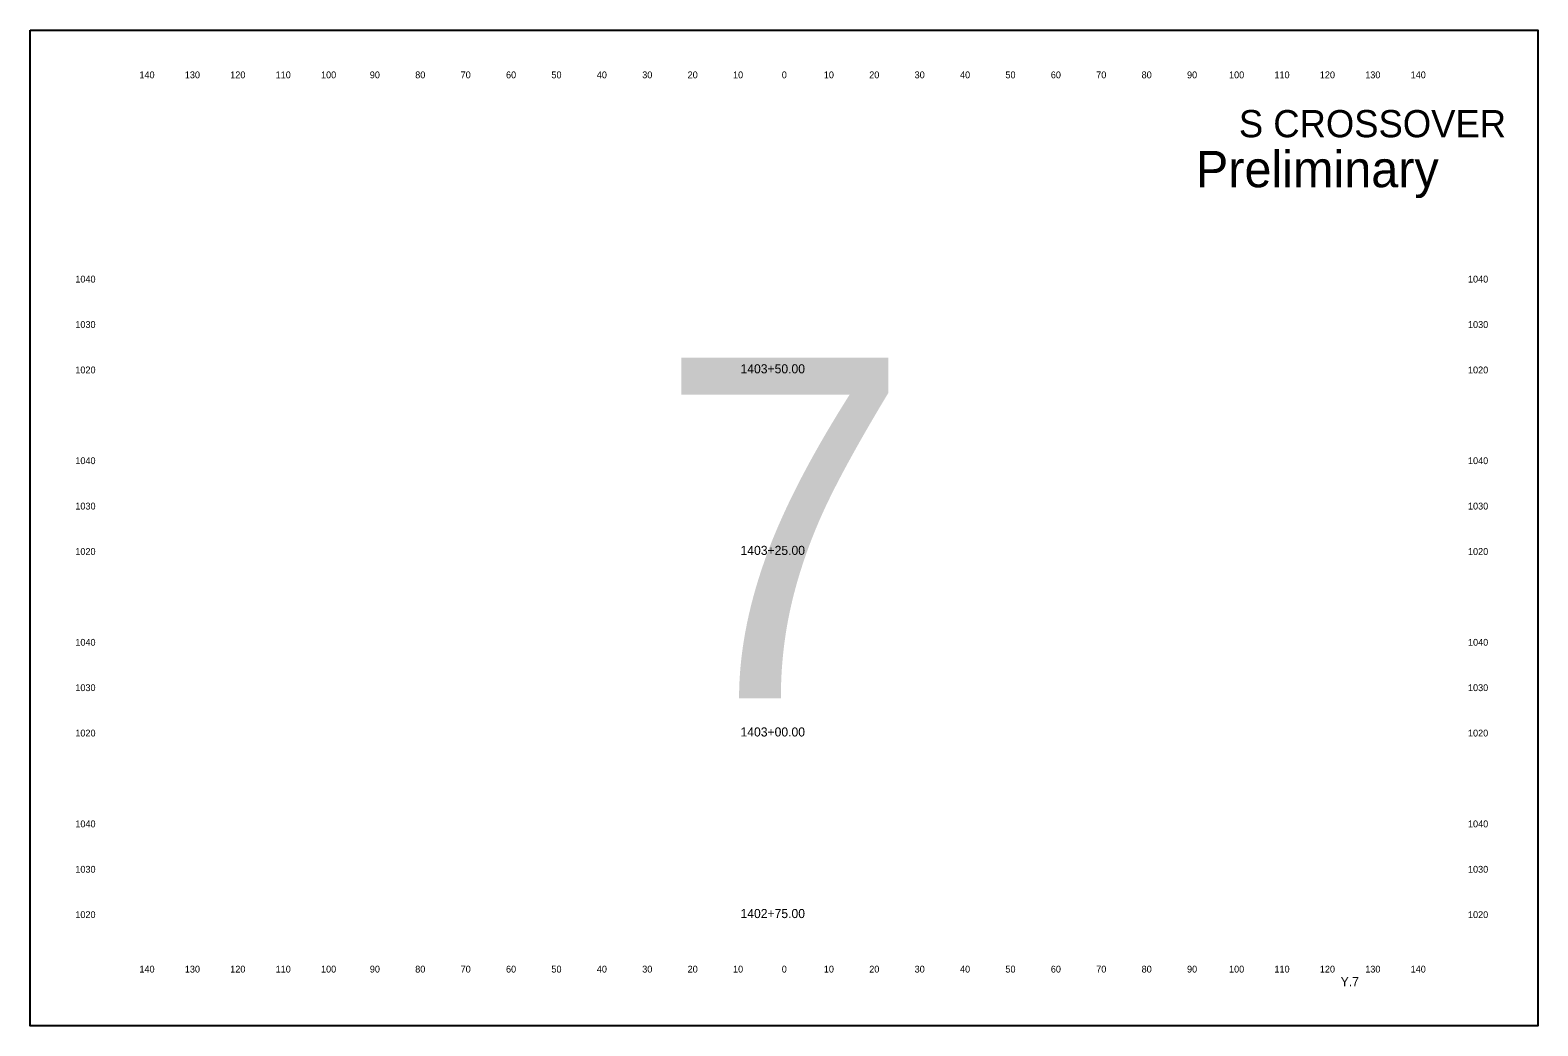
# Model space of a CAD drawing. Extents: x 10123 to 14768, y 9730 to 9950.
# Drawn here: x 12283.2 to 12615.3, y 9730.3 to 9949.6 of the extents above; entities that cross this region are included whole.
import ezdxf

# ---------------------------------------------------------------- set-up
doc = ezdxf.new("R2010")
doc.units = 0
for name, color, linetype in [('dsnTextCpn', 7, 'Continuous'), ('dsnTextCpnTitleSheetLocDesc', 7, 'Continuous'), ('dsnTextCpnTitleSheetPIN', 7, 'Continuous'), ('dsnTextCpnTitleSheetWorkType', 7, 'Continuous')]:
    doc.layers.add(name, color=color, linetype=linetype)

msp = doc.modelspace()

# ---------------------------------------------------------------- linework, layer by layer
at = {"layer": 'dsnTextCpnTitleSheetWorkType'}
msp.add_lwpolyline([(12283.21, 9949.6), (12615.29, 9949.6), (12615.29, 9730.26), (12283.21, 9730.26)], close=True, dxfattribs=at)

# ---------------------------------------------------------------- texts
at = {"layer": 'dsnTextCpn'}
for s, height, p in [('140', 1.5, (12307.27, 9939)), ('130', 1.5, (12317.27, 9939)), ('120', 1.5, (12327.27, 9939)), ('110', 1.5, (12337.27, 9939)), ('100', 1.5, (12347.27, 9939)), ('90', 1.5, (12358.02, 9939)), ('80', 1.5, (12368.02, 9939)), ('70', 1.5, (12378.02, 9939)), ('60', 1.5, (12388.02, 9939)), ('50', 1.5, (12398.02, 9939)), ('40', 1.5, (12408.02, 9939)), ('30', 1.5, (12418.02, 9939)), ('20', 1.5, (12428.02, 9939)), ('10', 1.5, (12438.02, 9939)), ('0', 1.5, (12448.76, 9939)), ('0', 1.5, (12448.76, 9939)), ('10', 1.5, (12458.02, 9939)), ('20', 1.5, (12468.02, 9939)), ('30', 1.5, (12478.02, 9939)), ('40', 1.5, (12488.02, 9939)), ('50', 1.5, (12498.02, 9939)), ('60', 1.5, (12508.02, 9939)), ('70', 1.5, (12518.02, 9939)), ('80', 1.5, (12528.02, 9939)), ('90', 1.5, (12538.02, 9939)), ('100', 1.5, (12547.27, 9939)), ('110', 1.5, (12557.27, 9939)), ('120', 1.5, (12567.27, 9939)), ('130', 1.5, (12577.27, 9939)), ('140', 1.5, (12587.27, 9939)), ('S CROSSOVER', 6, (12549.44, 9926)), ('1040', 1.5, (12293.15, 9894)), ('1040', 1.5, (12599.9, 9894)), ('1030', 1.5, (12293.15, 9884)), ('1030', 1.5, (12599.9, 9884)), ('1020', 1.5, (12293.15, 9874)), ('1403+50.00', 2, (12439.67, 9874)), ('1020', 1.5, (12599.9, 9874)), ('1040', 1.5, (12293.15, 9854)), ('1040', 1.5, (12599.9, 9854)), ('1030', 1.5, (12293.15, 9844)), ('1030', 1.5, (12599.9, 9844)), ('1020', 1.5, (12293.15, 9834)), ('1403+25.00', 2, (12439.67, 9834)), ('1020', 1.5, (12599.9, 9834)), ('1040', 1.5, (12293.15, 9814)), ('1040', 1.5, (12599.9, 9814)), ('1030', 1.5, (12293.15, 9804)), ('1030', 1.5, (12599.9, 9804)), ('1020', 1.5, (12293.15, 9794)), ('1403+00.00', 2, (12439.67, 9794)), ('1020', 1.5, (12599.9, 9794)), ('1040', 1.5, (12293.15, 9774)), ('1040', 1.5, (12599.9, 9774)), ('1030', 1.5, (12293.15, 9764)), ('1030', 1.5, (12599.9, 9764)), ('1020', 1.5, (12293.15, 9754)), ('1402+75.00', 2, (12439.67, 9754)), ('1020', 1.5, (12599.9, 9754)), ('140', 1.5, (12307.27, 9742)), ('130', 1.5, (12317.27, 9742)), ('120', 1.5, (12327.27, 9742)), ('110', 1.5, (12337.27, 9742)), ('100', 1.5, (12347.27, 9742)), ('90', 1.5, (12358.02, 9742)), ('80', 1.5, (12368.02, 9742)), ('70', 1.5, (12378.02, 9742)), ('60', 1.5, (12388.02, 9742)), ('50', 1.5, (12398.02, 9742)), ('40', 1.5, (12408.02, 9742)), ('30', 1.5, (12418.02, 9742)), ('20', 1.5, (12428.02, 9742)), ('10', 1.5, (12438.02, 9742)), ('0', 1.5, (12448.76, 9742)), ('0', 1.5, (12448.76, 9742)), ('10', 1.5, (12458.02, 9742)), ('20', 1.5, (12468.02, 9742)), ('30', 1.5, (12478.02, 9742)), ('40', 1.5, (12488.02, 9742)), ('50', 1.5, (12498.02, 9742)), ('60', 1.5, (12508.02, 9742)), ('70', 1.5, (12518.02, 9742)), ('80', 1.5, (12528.02, 9742)), ('90', 1.5, (12538.02, 9742)), ('100', 1.5, (12547.27, 9742)), ('110', 1.5, (12557.27, 9742)), ('120', 1.5, (12567.27, 9742)), ('130', 1.5, (12577.27, 9742)), ('140', 1.5, (12587.27, 9742))]:
    msp.add_text(s, height=height, dxfattribs=at).set_placement(p)
at = {"layer": 'dsnTextCpnTitleSheetLocDesc'}
msp.add_text('Preliminary', height=8, dxfattribs=at).set_placement((12539.97, 9915))
at = {"layer": 'dsnTextCpnTitleSheetPIN'}
msp.add_text('Y.7', height=2, dxfattribs=at).set_placement((12571.86, 9739))
at = {"layer": 'dsnTextCpnTitleSheetWorkType'}
msp.add_text('7', height=75, dxfattribs=at).set_placement((12421.48, 9802.43))

doc.saveas('drawing.dxf')
